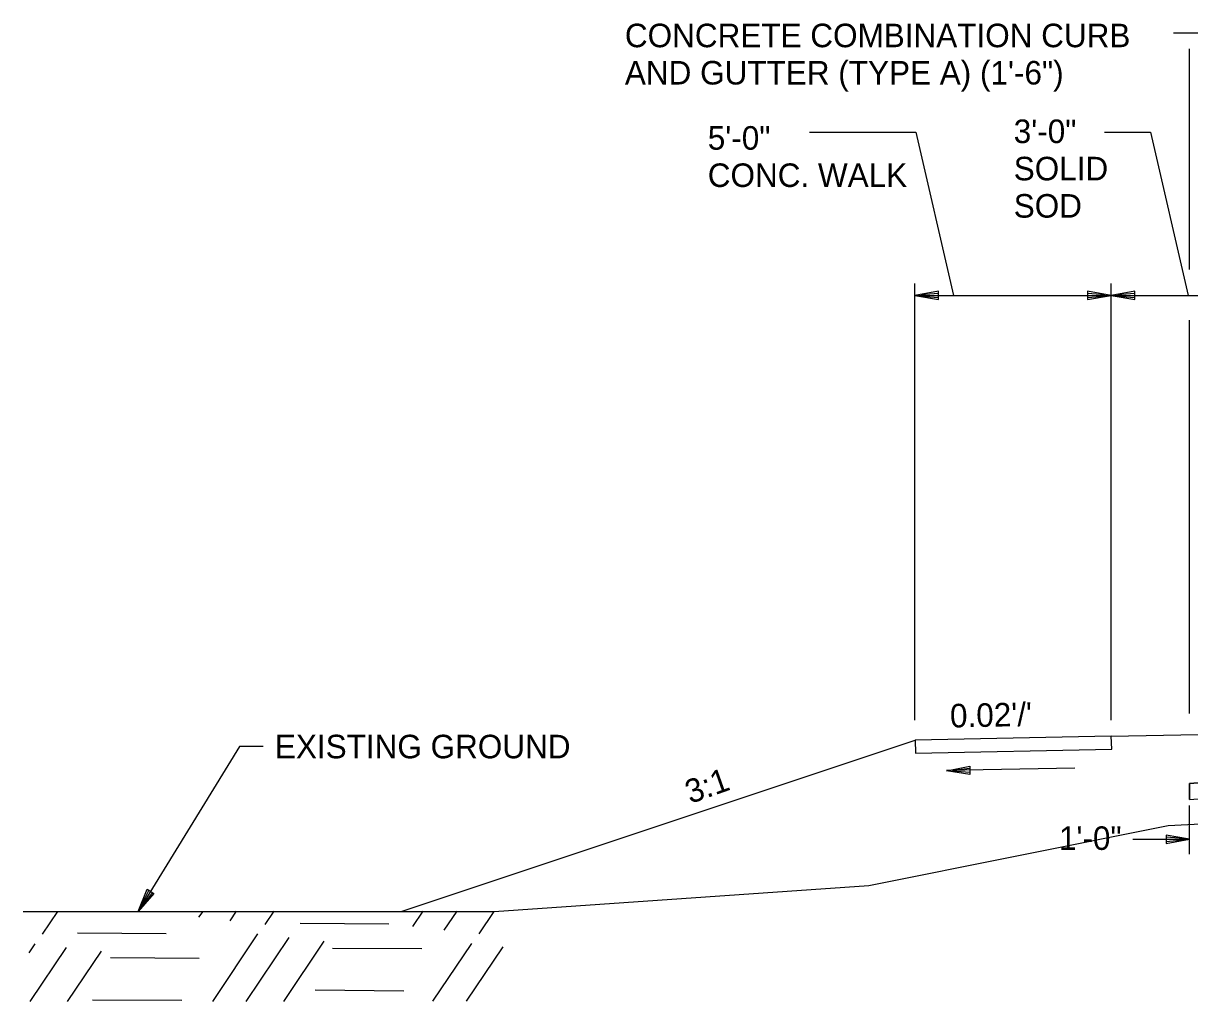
# Model space of a CAD drawing. Extents: x 1001270 to 1003428, y 1840152 to 1842912.
# Drawn here: x 1001296.14 to 1001325.87, y 1842245.17 to 1842270.1 of the extents above; entities that cross this region are included whole.
import ezdxf

# ---------------------------------------------------------------- set-up
doc = ezdxf.new("R2010")
doc.units = 0
for name, color, linetype in [('19', 7, 'Continuous'), ('20', 7, 'Continuous'), ('8', 7, 'Continuous')]:
    doc.layers.add(name, color=color, linetype=linetype)

# ---------------------------------------------------------------- blocks, each defined once
blk = doc.blocks.new('TM')
at = {"layer": '8'}
for p, q in [((-120.309, 21.181), (-119.787, -20.829)), ((0, 0), (-120.309, 21.181)), ((-31.382, 2.945), (-120.176, 10.512)), ((-119.787, -20.829), (0, 0)), ((-119.911, -10.826), (-31.307, -3.057))]:
    blk.add_line(p, q, dxfattribs=at)

msp = doc.modelspace()

# ---------------------------------------------------------------- linework, layer by layer
at = {"layer": '19'}
for p, q in [((1001325.458, 1842269.86), (1001326.637, 1842269.86)), ((1001325.868, 1842263.832), (1001325.868, 1842269.449)), ((1001316.183, 1842267.326), (1001318.891, 1842267.326)), ((1001318.891, 1842267.326), (1001319.847, 1842263.169)), ((1001323.694, 1842267.326), (1001324.873, 1842267.326)), ((1001324.873, 1842267.326), (1001325.83, 1842263.169)), ((1001318.868, 1842252.346), (1001318.868, 1842263.469)), ((1001319.468, 1842263.274), (1001318.868, 1842263.169)), ((1001319.468, 1842263.219), (1001319.028, 1842263.184)), ((1001319.468, 1842263.064), (1001319.468, 1842263.274)), ((1001323.268, 1842263.274), (1001323.268, 1842263.064)), ((1001323.868, 1842263.169), (1001323.268, 1842263.274)), ((1001323.708, 1842263.184), (1001323.268, 1842263.219)), ((1001323.868, 1842252.346), (1001323.868, 1842263.469)), ((1001324.468, 1842263.274), (1001323.868, 1842263.169)), ((1001324.468, 1842263.219), (1001324.028, 1842263.184)), ((1001324.468, 1842263.064), (1001324.468, 1842263.274)), ((1001318.868, 1842263.169), (1001328.368, 1842263.169)), ((1001318.868, 1842263.169), (1001319.468, 1842263.064)), ((1001319.028, 1842263.154), (1001319.468, 1842263.114)), ((1001323.268, 1842263.064), (1001323.868, 1842263.169)), ((1001323.268, 1842263.114), (1001323.708, 1842263.154)), ((1001323.868, 1842263.169), (1001324.468, 1842263.064)), ((1001324.028, 1842263.154), (1001324.468, 1842263.114)), ((1001325.868, 1842252.517), (1001325.868, 1842262.54)), ((1001323.87, 1842251.942), (1001318.871, 1842251.841)), ((1001323.87, 1842251.942), (1001326.868, 1842252.001)), ((1001323.883, 1842251.609), (1001323.87, 1842251.942)), ((1001323.87, 1842251.942), (1001323.87, 1842251.942)), ((1001305.774, 1842247.476), (1001318.871, 1842251.841)), ((1001318.871, 1842251.841), (1001318.884, 1842251.509)), ((1001318.884, 1842251.509), (1001323.883, 1842251.609)), ((1001325.868, 1842250.324), (1001325.868, 1842250.731)), ((1001325.868, 1842250.731), (1001325.868, 1842250.324)), ((1001325.868, 1842248.935), (1001325.868, 1842250.173)), ((1001324.419, 1842249.313), (1001325.868, 1842249.313)), ((1001324.419, 1842249.313), (1001325.868, 1842249.313)), ((1001325.268, 1842249.418), (1001325.268, 1842249.208)), ((1001325.868, 1842249.313), (1001325.268, 1842249.418)), ((1001325.268, 1842249.418), (1001325.268, 1842249.208)), ((1001325.868, 1842249.313), (1001325.268, 1842249.418)), ((1001325.708, 1842249.328), (1001325.268, 1842249.363)), ((1001325.708, 1842249.328), (1001325.268, 1842249.363)), ((1001325.268, 1842249.208), (1001325.868, 1842249.313)), ((1001325.268, 1842249.208), (1001325.868, 1842249.313)), ((1001325.268, 1842249.258), (1001325.708, 1842249.298)), ((1001325.268, 1842249.258), (1001325.708, 1842249.298)), ((1001299.073, 1842247.476), (1001299.297, 1842248.042)), ((1001299.297, 1842248.042), (1001299.474, 1842247.933)), ((1001299.474, 1842247.933), (1001299.073, 1842247.476)), ((1001299.147, 1842247.617), (1001299.34, 1842248.01)), ((1001299.433, 1842247.954), (1001299.17, 1842247.605)), ((1001296.634, 1842246.891), (1001297.026, 1842247.474)), ((1001300.619, 1842247.325), (1001300.725, 1842247.475)), ((1001301.414, 1842247.234), (1001301.58, 1842247.478)), ((1001302.309, 1842247.141), (1001302.535, 1842247.48)), ((1001306.074, 1842247.086), (1001306.335, 1842247.481)), ((1001306.868, 1842246.994), (1001307.2, 1842247.483)), ((1001307.764, 1842246.902), (1001308.144, 1842247.476)), ((1001303.197, 1842247.171), (1001305.458, 1842247.159)), ((1001297.523, 1842246.93), (1001299.782, 1842246.909)), ((1001300.971, 1842245.178), (1001302.124, 1842246.899)), ((1001296.294, 1842246.423), (1001296.448, 1842246.649)), ((1001296.317, 1842245.175), (1001297.243, 1842246.557)), ((1001301.826, 1842245.181), (1001302.918, 1842246.807)), ((1001302.781, 1842245.183), (1001303.814, 1842246.715)), ((1001304.027, 1842246.542), (1001306.298, 1842246.53)), ((1001306.582, 1842245.184), (1001307.578, 1842246.66)), ((1001307.436, 1842245.186), (1001308.373, 1842246.568)), ((1001297.272, 1842245.177), (1001298.138, 1842246.465)), ((1001298.363, 1842246.301), (1001300.622, 1842246.28)), ((1001303.585, 1842245.472), (1001305.845, 1842245.451)), ((1001297.91, 1842245.222), (1001300.18, 1842245.209))]:
    msp.add_line(p, q, dxfattribs=at)
for points in [[(1001308.144, 1842247.476), (1001317.69, 1842248.135), (1001325.322, 1842249.662), (1001329.477, 1842249.873), (1001334.361, 1842250.698), (1001340.15, 1842250.916), (1001346.517, 1842251.442), (1001351.216, 1842251.762), (1001358.361, 1842252.546), (1001362.7, 1842252.61), (1001370.347, 1842252.736), (1001372.903, 1842253.368), (1001376.995, 1842256.283), (1001381.307, 1842257.932), (1001385.954, 1842258.619), (1001388.908, 1842258.834)], [(1001366.868, 1842253.658), (1001364.368, 1842253.705), (1001325.868, 1842250.731)], [(1001325.868, 1842250.324), (1001364.368, 1842253.288), (1001366.868, 1842253.238)], [(1001325.868, 1842250.324), (1001346.361, 1842251.902)], [(1001302.256, 1842251.675), (1001301.656, 1842251.675), (1001299.073, 1842247.476)], [(1001325.868, 1842250.731), (1001326.868, 1842250.808)], [(1001296.144, 1842247.476), (1001308.144, 1842247.476)]]:
    msp.add_lwpolyline(points, dxfattribs=at)
at = {"layer": '20'}
msp.add_line((1001322.938, 1842251.126), (1001319.668, 1842251.061), dxfattribs=at)

# ---------------------------------------------------------------- block references
at = {"layer": '19', "xscale": 0.0050063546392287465, "yscale": -0.0050063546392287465, "rotation": -178.8781640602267}
msp.add_blockref('TM', (1001319.667, 1842251.059), dxfattribs=at)

# ---------------------------------------------------------------- texts
at = {"layer": '19'}
for s, rotation, p in [('CONCRETE COMBINATION CURB', 360, (1001311.475, 1842269.493)), ('AND GUTTER (TYPE A) (1\'-6")', 360, (1001311.475, 1842268.543)), ('3\'-0"', 360, (1001321.384, 1842267.051)), ('5\'-0"', 360, (1001313.587, 1842266.882)), ('CONC. WALK', 360, (1001313.587, 1842265.932)), ('SOLID ', 360, (1001321.384, 1842266.101)), ('SOD', 360, (1001321.384, 1842265.151)), ("0.02'/'", 1.1496, (1001319.766, 1842252.159)), ('3:1', 19.5057, (1001313.142, 1842250.211))]:
    msp.add_text(s, height=0.6, rotation=rotation, dxfattribs=at).set_placement(p)
for s, p in [('EXISTING GROUND', (1001302.556, 1842251.375)), ('1\'-0"', (1001322.536, 1842249.041))]:
    msp.add_text(s, height=0.6, dxfattribs=at).set_placement(p)

doc.saveas('drawing.dxf')
